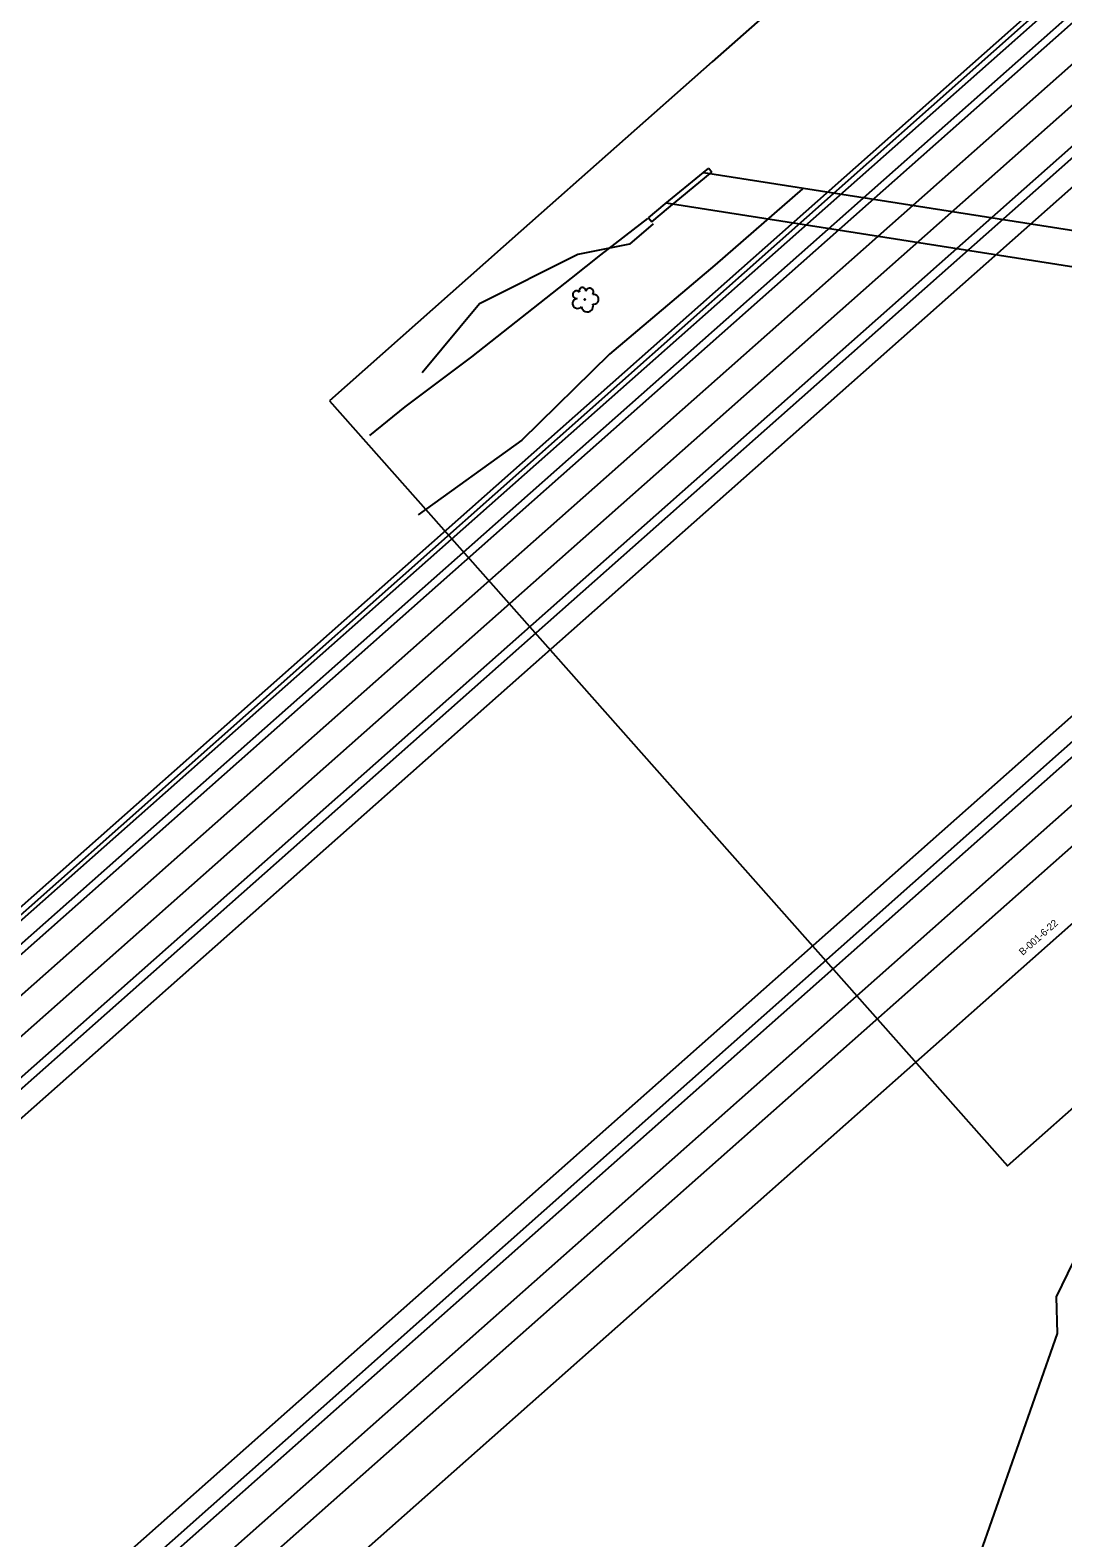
# Model space of a CAD drawing. Extents: x 2265470 to 2269397, y 712607 to 716300.
# Drawn here: x 2267391 to 2267795, y 714269 to 714859 of the extents above; entities that cross this region are included whole.
import ezdxf

# ---------------------------------------------------------------- set-up
doc = ezdxf.new("R2010")
doc.units = 0
for name, color, linetype in [('BD_P_Text', 7, 'Continuous'), ('BR_X_SV_Abut_Text', 7, 'Continuous'), ('DR_X_Elev_Flow', 7, 'Continuous'), ('GE_X_Alignment', 7, 'Continuous'), ('GE_X_Cells', 7, 'Continuous'), ('GT_Project_Soil_Boring', 7, 'Continuous'), ('GT_Project_Text', 7, 'Continuous'), ('HY_X_Water_Edge', 7, 'Continuous'), ('PM_P_Cells', 7, 'Continuous'), ('SC_Scratch1', 7, 'Continuous'), ('SC_Scratch9', 7, 'Continuous'), ('SV_X_Control_Cells_Found', 7, 'Continuous'), ('SV_X_Mon_Cells_Found', 7, 'Continuous'), ('TX_X_20', 7, 'Continuous')]:
    doc.layers.add(name, color=color, linetype=linetype)

msp = doc.modelspace()

# ---------------------------------------------------------------- linework, layer by layer
at = {"layer": 'BD_P_Text'}
for p, q in [((2265487.76, 712798.68), (2269337.69, 716208.98)), ((2265495.72, 712789.7), (2269345.65, 716200)), ((2265628.32, 712633.29), (2269392.86, 715967.96)), ((2265635.88, 712623.96), (2269394.26, 715953.16))]:
    msp.add_line(p, q, dxfattribs=at)
at = {"layer": 'BR_X_SV_Abut_Text'}
for points in [[(2267792.33, 714363.24), (2267825.85, 714432.22), (2267885.14, 714521.28), (2267920.97, 714551.08)], [(2267431.54, 713602.63), (2267430.01, 713603.52), (2267436, 713766.8), (2267443.15, 713793.97), (2267478.79, 713884.82), (2267551.68, 713986.83), (2267591.16, 714021.22), (2267649.39, 714086.13), (2267741.22, 714225.86), (2267760.89, 714258.07), (2267792.69, 714348.85), (2267792.33, 714363.24)]]:
    msp.add_lwpolyline(points, dxfattribs=at)
at = {"layer": 'DR_X_Elev_Flow'}
msp.add_lwpolyline([(2267693, 714796.76), (2267658.66, 714766.88), (2267617.42, 714732.04), (2267583.09, 714698.39), (2267542.53, 714669.14)], dxfattribs=at)
at = {"layer": 'GE_X_Alignment'}
for p, q in [((2265479.81, 712807.66), (2269338.54, 716225.76)), ((2265503.68, 712780.71), (2269349.21, 716187.12)), ((2265619.44, 712644.24), (2269391.23, 715985.32))]:
    msp.add_line(p, q, dxfattribs=at)
at = {"layer": 'GE_X_Cells'}
msp.add_line((2267833.34, 714908.85), (2266756.38, 713952.79), dxfattribs=at)
at = {"layer": 'GT_Project_Text'}
for p, q in [((2266699.26, 713906.57), (2269235.28, 716152.99)), ((2266703.72, 713827.7), (2269255.45, 716088.03)), ((2266674.89, 713595.2), (2269268.85, 715892.94)), ((2265650.54, 712606.64), (2269309.14, 715847.46))]:
    msp.add_line(p, q, dxfattribs=at)
at = {"layer": 'HY_X_Water_Edge'}
msp.add_circle((2267607.81, 714753.47), 0.24, dxfattribs=at)
for centre, radius, start, end in [((2267604.5, 714755.33), 1.47, 39.06254, 279.54124), ((2267606.82, 714756.83), 1.32, 354.0047, 205.97412), ((2267609.63, 714756.3), 1.55, 323.82996, 165.0376), ((2267604.95, 714751.92), 1.97, 96.17219, 320.57371), ((2267608.75, 714750.86), 2.28, 184.94757, 19.45715), ((2267611.27, 714753.5), 1.91, 259.14531, 101.45961)]:
    msp.add_arc(centre, radius, start, end, dxfattribs=at)
at = {"layer": 'PM_P_Cells'}
msp.add_line((2265473.18, 712815.15), (2269331.91, 716233.24), dxfattribs=at)
at = {"layer": 'SC_Scratch1'}
for p, q in [((2266706.43, 713898.3), (2269234.59, 716137.76)), ((2266701.55, 713837.25), (2269251.37, 716095.9)), ((2266662.26, 713571.53), (2269272.16, 715889.2)), ((2267654.16, 714803.15), (2268111.44, 714731.41)), ((2267639.62, 714791.26), (2268097.26, 714719.47))]:
    msp.add_line(p, q, dxfattribs=at)
at = {"layer": 'SC_Scratch9'}
msp.add_lwpolyline([(2267507.89, 714713.84), (2267773.12, 714414.42), (2267847.98, 714480.73), (2267885.41, 714513.88), (2267922.83, 714547.03), (2267960.26, 714580.19), (2267997.69, 714613.34), (2268035.12, 714646.5), (2268072.54, 714679.65), (2268109.97, 714712.8), (2268147.4, 714745.96), (2268184.83, 714779.11), (2267919.6, 715078.53), (2267882.17, 715045.38), (2267844.74, 715012.22), (2267807.31, 714979.07), (2267769.89, 714945.92), (2267732.46, 714912.76), (2267695.03, 714879.61), (2267657.6, 714846.46), (2267620.18, 714813.3), (2267582.75, 714780.15)], close=True, dxfattribs=at)
at = {"layer": 'SV_X_Control_Cells_Found'}
msp.add_lwpolyline([(2267523.71, 714700.25), (2267537.42, 714711.5), (2267563.53, 714731.05), (2267602.55, 714761.8), (2267614.03, 714770.94), (2267632.45, 714785.15)], dxfattribs=at)
at = {"layer": 'SV_X_Mon_Cells_Found'}
msp.add_lwpolyline([(2267634.47, 714783.07), (2267625.27, 714775.12), (2267605, 714771.08), (2267566.52, 714751.77), (2267544.14, 714724.81)], dxfattribs=at)
at = {"layer": 'TX_X_20'}
for p, q in [((2267654.16, 714803.15), (2267656.27, 714804.83)), ((2267656.27, 714804.83), (2267657.52, 714803.26)), ((2267639.19, 714790.91), (2267654.16, 714803.15)), ((2267640.47, 714789.37), (2267655.42, 714801.59)), ((2267655.42, 714801.59), (2267657.52, 714803.26)), ((2267632.7, 714785.39), (2267639.19, 714790.91)), ((2267634, 714783.87), (2267640.47, 714789.37)), ((2267632.7, 714785.39), (2267634, 714783.87))]:
    msp.add_line(p, q, dxfattribs=at)

# ---------------------------------------------------------------- texts
at = {"layer": 'GT_Project_Soil_Boring'}
msp.add_text('B-001-6-22', height=2.8, rotation=41.53477, dxfattribs=at).set_placement((2267779.17, 714496.62))

doc.saveas('drawing.dxf')
